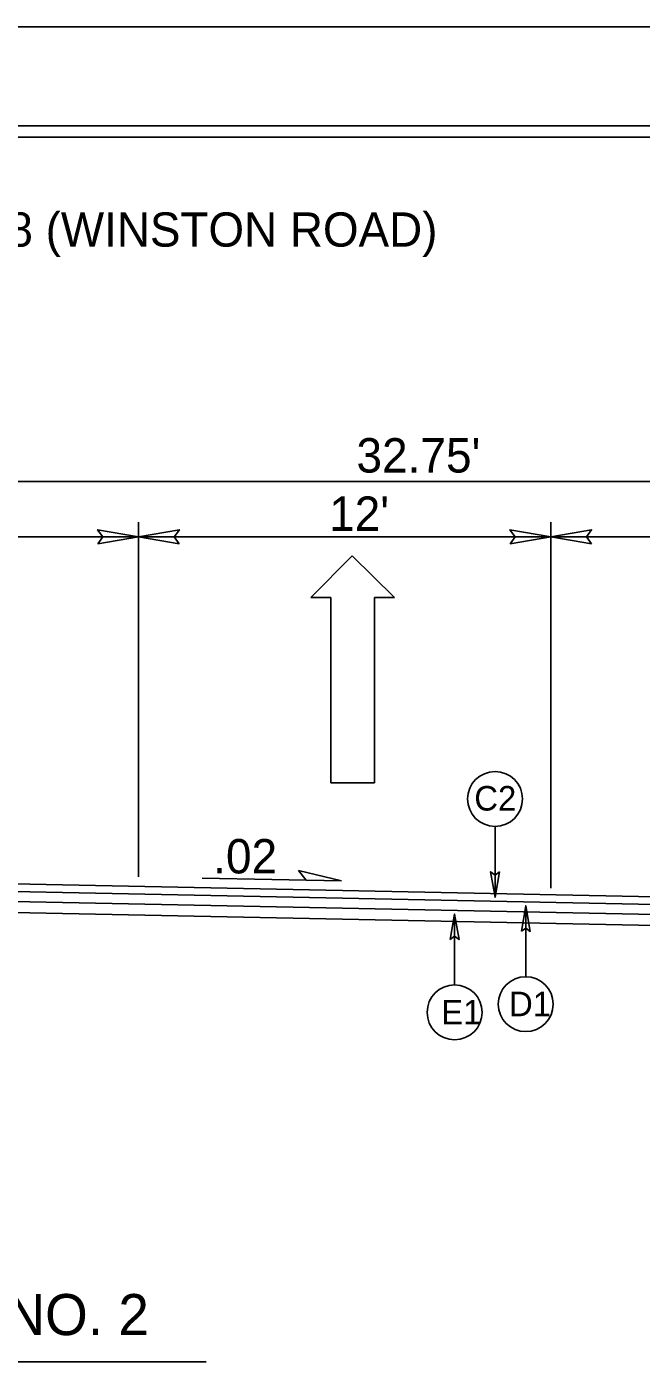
# Model space of a CAD drawing. Extents: x 957297 to 961629, y 830661 to 840840.
# Drawn here: x 959537.4 to 959676.7, y 839310.6 to 839615.4 of the extents above; entities that cross this region are included whole.
import ezdxf

# ---------------------------------------------------------------- set-up
doc = ezdxf.new("R2010")
doc.units = 0
for name, color, linetype in [('Old_Level_1', 7, 'Continuous'), ('Old_Level_11', 7, 'Continuous'), ('Prop Dimension Text', 7, 'Continuous'), ('Prop Lane Arrow CELL', 7, 'Continuous'), ('Sheet Plot Border Inside CELL', 7, 'Continuous'), ('Sheet Plot Border Outside CELL', 7, 'Continuous'), ('Sheet Typical CELL', 7, 'Continuous'), ('Typical ID Circle CELL', 7, 'Continuous'), ('Typical Terminator CELL', 7, 'Continuous'), ('Typical Text ID Circle CELL', 7, 'Continuous')]:
    doc.layers.add(name, color=color, linetype=linetype)

# ---------------------------------------------------------------- blocks, each defined once
blk = doc.blocks.new('Lane Arrow Through')
at = {"layer": 'Prop Lane Arrow CELL'}
for p, q in [((-3.15, 1.6), (-3.15, 3.1)), ((-3.15, 3.1), (0, 0)), ((-17.15, 1.6), (-3.15, 1.6)), ((-17.15, -1.7), (-17.15, 1.6)), ((0, 0), (-3.15, -3.2)), ((-3.15, -1.7), (-17.15, -1.7)), ((-3.15, -3.2), (-3.15, -1.7))]:
    blk.add_line(p, q, dxfattribs=at)

msp = doc.modelspace()

# ---------------------------------------------------------------- linework, layer by layer
at = {"layer": 'Old_Level_1'}
for p, q in [((959494.54, 839512.21), (959749.66, 839512.21)), ((959562.7, 839503.02), (959562.7, 839422.55)), ((959656.18, 839503.02), (959656.18, 839419.99)), ((959426.38, 839499.67), (959562.7, 839499.67)), ((959562.7, 839499.67), (959656.18, 839499.67)), ((959656.18, 839499.67), (959749.66, 839499.67)), ((959494.54, 839421.75), (959782.66, 839415.93)), ((959494.54, 839420.03), (959782.66, 839414.2)), ((959577.12, 839422.25), (959608.72, 839421.62)), ((959494.54, 839417.77), (959782.66, 839411.95)), ((959494.54, 839415.28), (959805.61, 839408.99)), ((959578.04, 839312.54), (959410.34, 839312.54))]:
    msp.add_line(p, q, dxfattribs=at)
at = {"layer": 'Old_Level_11'}
for p, q in [((959600.72, 839421.78), (959598.99, 839424.03)), ((959598.99, 839424.03), (959608.72, 839421.62)), ((959608.72, 839421.62), (959600.72, 839421.78))]:
    msp.add_line(p, q, dxfattribs=at)
at = {"layer": 'Sheet Plot Border Inside CELL'}
msp.add_lwpolyline([(960390.3, 839592.94), (958723.8, 839592.94), (958723.8, 838537.84), (960390.3, 838537.84)], close=True, dxfattribs=at)
at = {"layer": 'Sheet Plot Border Outside CELL'}
msp.add_lwpolyline([(960394.8, 839615.39), (958710.8, 839615.39), (958710.8, 838515.39), (960394.8, 838515.39)], close=True, dxfattribs=at)
at = {"layer": 'Sheet Typical CELL'}
msp.add_lwpolyline([(960377.8, 839590.39), (958877.8, 839590.39), (958877.8, 838540.39), (960377.8, 838540.39)], close=True, dxfattribs=at)
at = {"layer": 'Typical ID Circle CELL'}
for p, q in [((959643.55, 839434), (959643.55, 839417.91)), ((959634.38, 839398.03), (959634.38, 839414.12)), ((959650.51, 839399.89), (959650.51, 839415.98))]:
    msp.add_line(p, q, dxfattribs=at)
for centre in [(959643.55, 839440.22), (959650.51, 839393.67), (959634.38, 839391.81)]:
    msp.add_circle(centre, 6.23, dxfattribs=at)
at = {"layer": 'Typical Terminator CELL'}
for points in [[(959553.48, 839498.08), (959562.7, 839499.67), (959553.43, 839501.3), (959554.61, 839499.67)], [(959571.92, 839498.08), (959562.7, 839499.67), (959571.98, 839501.3), (959570.8, 839499.67)], [(959646.96, 839498.08), (959656.18, 839499.67), (959646.91, 839501.3), (959648.09, 839499.67)], [(959665.4, 839498.08), (959656.18, 839499.67), (959665.46, 839501.3), (959664.28, 839499.67)], [(959644.54, 839423.67), (959643.55, 839417.91), (959642.52, 839423.71), (959643.55, 839422.97)], [(959633.39, 839408.35), (959634.38, 839414.12), (959635.4, 839408.32), (959634.38, 839409.06)], [(959649.52, 839410.22), (959650.51, 839415.98), (959651.54, 839410.18), (959650.51, 839410.92)]]:
    msp.add_lwpolyline(points, close=True, dxfattribs=at)

# ---------------------------------------------------------------- block references
at = {"layer": 'Old_Level_1', "xscale": 3, "yscale": 3, "rotation": 90}
msp.add_blockref('Lane Arrow Through', (959611.11, 839495.36), dxfattribs=at)

# ---------------------------------------------------------------- texts
at = {"layer": 'Old_Level_1'}
msp.add_text('TYPICAL SECTION NO. 2', height=9.3239, dxfattribs=at).set_placement((959418.18, 839318.58))
at = {"layer": 'Prop Dimension Text'}
for s, height, rotation, p in [('-L- NC 8 (WINSTON ROAD)', 7.7675, 0, (959499.5, 839565.53)), ("32.75'", 7.801, 0, (959612.12, 839514.28)), ("12'", 7.801, 0, (959605.92, 839501.05)), ('.02', 7.801, 360, (959579.63, 839423.33))]:
    msp.add_text(s, height=height, rotation=rotation, dxfattribs=at).set_placement(p)
at = {"layer": 'Typical Text ID Circle CELL'}
for s, p in [('C2', (959638.84, 839437.59)), ('D1', (959646.72, 839390.93)), ('E1', (959631.35, 839389.06))]:
    msp.add_text(s, height=5.572, dxfattribs=at).set_placement(p)

doc.saveas('drawing.dxf')
